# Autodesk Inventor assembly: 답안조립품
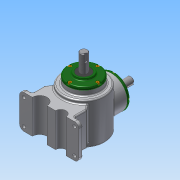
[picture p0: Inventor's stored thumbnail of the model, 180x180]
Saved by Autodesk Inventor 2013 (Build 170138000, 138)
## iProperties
Created: 2018-08
Part Number: 답안조립품
Document SubType Name: Weldment
Designer: Administrator
Weld Material: Welded Aluminum-6061
Author: Administrator
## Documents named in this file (14)
- C:\Users\Administrator\Desktop\480808V1012\답안조립품.iam
- C:\Users\Administrator\Desktop\480808V1012\본체.ipt
- C:\Users\Administrator\Desktop\480808V1012\메인 베벨기어.ipt
- C:\Users\Administrator\Desktop\480808V1012\메인 축.ipt
- 메인 축.ipt
- C:\Users\Administrator\Desktop\480808V1012\베어링 6203.ipt
- C:\Users\Administrator\Desktop\480808V1012\볼트 M4.ipt
- C:\Users\Administrator\Desktop\480808V1012\서브 베벨기어.ipt
- C:\Users\Administrator\Desktop\480808V1012\서브 축.ipt
- 서브 축.ipt
- C:\Users\Administrator\Desktop\480808V1012\오일실 17 32 8.ipt
- C:\Users\Administrator\Desktop\480808V1012\커버.ipt
- C:\Users\Administrator\Desktop\480808V1012\키 4x4.ipt
- C:\Users\Administrator\Desktop\480808V1012\키 5x5.ipt
